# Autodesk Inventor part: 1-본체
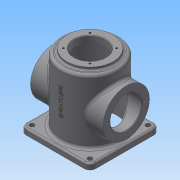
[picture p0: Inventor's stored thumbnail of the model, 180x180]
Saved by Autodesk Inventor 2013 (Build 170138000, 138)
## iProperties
Created: 2015-10
Part Number: 1-본체
Material: 일반
Document SubType Name: Modeling
Designer: semtle
Density: 1 g/cm^3
Author: semtle
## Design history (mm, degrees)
sketch "스케치1"
  geometry: L1 (-60, 60)-(60, 60); L2 (60, 60)-(60, -60); L3 (60, -60)-(-60, -60); L4 (-60, -60)-(-60, 60); C1 r 4 at (-50, 50); C2 r 4 at (50, 50); C3 r 4 at (50, -50); C4 r 4 at (-50, -50); 3 further points
  constraints: 8 end point, 4 centre point, 3 equal radius, 3 horizontal alignment, 3 vertical alignment, 2 midpoint, 2 parallel, 1 horizontal, 1 perpendicular
  dimensions: "d0" = 120 distance of L1.start L1.end; "d2" = 120 distance of L1.end L2.end; "d3" = 100 distance of C2.centre C1.centre; "d4" = 50 horizontal distance of C2.centre point (0, 0); "d5" = 100 distance of C3.centre C2.centre; "d6" = 50 horizontal distance of C3.centre point (0, 0); "d7" = 8 diameter of C2
extrude "돌출1" new body sketch "스케치1" distance "d8" = 10; taper "d9" = 0 deg
sketch "스케치2"
  geometry: C1 r 50 at (0, 0); 1 further point
  constraints: 1 centre point, 1 coincident
  dimensions: "d10" = 100 diameter of C1
extrude "돌출2" join sketch "스케치2" distance "d12" = 110; taper "d13" = 0 deg
sketch "스케치4"
  geometry: C1 r 45 at (0, 0); 1 further point
  constraints: 1 centre point, 1 coincident
  dimensions: "d16" = 90 diameter of C1
extrude "돌출4" cut sketch "스케치4" distance "d19" = 112; taper "d20" = 0 deg
sketch "스케치5"
  geometry: C1 r 50 at (0, 0) reference; C2 r 40 at (0, 0)
  constraints: 1 centre point, 1 coincident
  dimensions: "d21" = 80 diameter of C2
extrude "돌출5" join sketch "스케치5" distance "d23" = 5; taper "d24" = 0 deg
sketch "스케치6"
  geometry: C1 r 40 at (0, 0) reference; C2 r 27 at (0, 0)
  constraints: 1 centre point, 1 coincident
  dimensions: "d25" = 54 diameter of C2
extrude "돌출6" cut sketch "스케치6" distance "d27" = 13; taper "d28" = 0 deg
node "작업 평면1"
sketch "스케치7"
  geometry: L1 (50, 110)-(-50, 110) reference; L2 (-50, 0)-(50, 0) reference; L3 (45, -10)-(-45, -10) reference; 3 further points
  constraints: 1 midpoint, 1 vertical alignment, 1 other
  dimensions: "d29" = 70 distance from line of point (0, 60) L3
feature "엠보싱1" sketch "스케치7" dims "d0" = 120, "d2" = 120, "d30" = 0.5, "d31" = 0
sketch "스케치8"
  geometry: L1 (60, 60)-(-60, 60) reference; L2 (-60, 60)-(-60, -60) reference; L3 (-60, -60)-(60, -60) reference; L4 (60, -60)-(60, 60) reference; C1 r 27 at (0, 0) reference; C2 r 50 at (0, 0) reference; C3 r 4 at (-50, -50) reference; C4 r 4 at (50, -50) reference; C5 r 4 at (50, 50) reference; C6 r 4 at (-50, 50) reference; A1 r 32.5 centre (0, 0) between (-22.981, 22.981) and (22.981, 22.981); 2 further points
  constraints: 4 point on circle, 2 horizontal alignment, 2 vertical alignment, 1 centre point, 1 coincident
  dimensions: "d32" = 65 diameter of A1; "d34" = 90 deg dimension on C1.centre A1.end A1.start
hole "구멍1" sketch "스케치8" at (-22.981, 22.981), (22.981, 22.981), (22.981, -22.981), (-22.981, -22.981) diameter "d36" = 3.242; stored, may be unused: countersink angle "d40" = 90 deg, drill point angle "d42" = 118 deg; dims "d37" = 8, "d38" = 4, "d39" = 2, "d41" = 10
node "작업 평면2"
sketch "스케치9"
  geometry: C1 r 40 at (0, 60); 1 further point
  constraints: 1 centre point, 1 vertical alignment
  dimensions: "d44" = 60 distance of C1.centre point (0, 0); "d45" = 80 diameter of C1
extrude "돌출7" join sketch "스케치9" stored distance "d46" = 13; taper "d47" = 0 deg
sketch "스케치10"
  geometry: C1 r 40 at (0, 0) reference; C2 r 27 at (0, 0); 1 further point
  constraints: 1 centre point, 1 coincident
  dimensions: "d48" = 54 diameter of C2
extrude "돌출8" cut sketch "스케치10" stored distance "d50" = 13; taper "d51" = 0 deg
sketch "스케치11"
  geometry: C1 r 27 at (0, 0) reference; C2 r 40 at (0, 0) reference; A1 r 32.5 centre (0, 0) between (0, 32.5) and (0, -32.5); 3 further points
  constraints: 4 point on circle, 2 horizontal alignment, 2 vertical alignment, 1 centre point, 1 coincident
  dimensions: "d52" = 65 diameter of A1
hole "구멍2" sketch "스케치11" at (0, 32.5), (0, -32.5), (32.5, 0), (-32.5, 0) diameter "d54" = 3.242; stored, may be unused: countersink angle "d58" = 90 deg, drill point angle "d60" = 118 deg; dims "d55" = 8, "d56" = 4, "d57" = 2, "d59" = 10
chamfer "모따기1" distance "d61" = 3; stored, may be unused: second distance "d62" = 2, angle "d63" = 45 deg
chamfer "모따기2" distance "d64" = 1; stored, may be unused: second distance "d65" = 2, angle "d66" = 45 deg
fillet "모깎기1" dims "d67" = 5
fillet "모깎기2" dims "d68" = 10
fillet "모깎기3" dims "d69" = 5
fillet "모깎기4" dims "d70" = 3
fillet "모깎기5" dims "d71" = 3
fillet "모깎기6" dims "d72" = 3
node "솔리드1"
mirror "대칭1"
node "투영된 루프1"
node "투영된 루프2"
other parameters: "d43" = 62.5
